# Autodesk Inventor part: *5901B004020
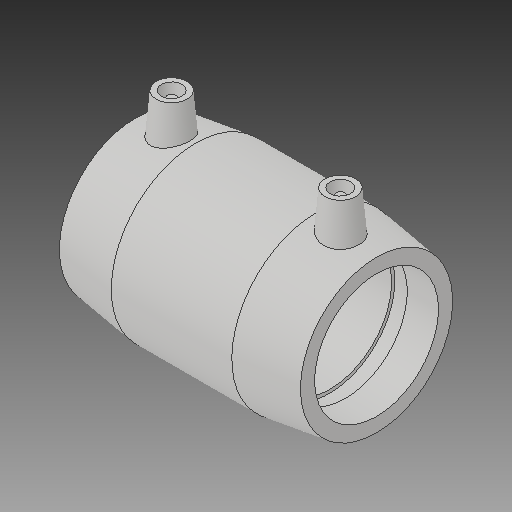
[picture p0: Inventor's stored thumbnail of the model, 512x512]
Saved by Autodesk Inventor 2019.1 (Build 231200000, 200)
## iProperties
Created: 2017-06
Part Number: *5901B004020
Material: Generic
Description: PLASSON IPS COUPLER 2''
Document SubType Name: Modeling
Designer: KIM
Mass: 8622.19 g
Surface Area: 6772.47 cm^2
Volume: 8622.19 cm^3
Density: 1 g/cm^3
Appearance: Default
Author: KIM
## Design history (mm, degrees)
derived "5901B.ipt"
feature "Solid1::5901B.ipt"
tag "TaggingFeature1"
body "Solid1"
other parameters: "d0" = 117.094, "d1" = 60.1, "d2" = 82.042, "d3" = 56.896, "d4" = 29.2735, "d5" = 73.8378, "d6" = 48.08, "d7" = 60.1, "d8" = 168 deg, "d10" = 22.7584, "d11" = 7.58613, "d13" = 117.094, "d14" = 17.6296, "d18" = 60.1, "d19" = 3.52592, "d20" = 168 deg, "d22" = 77.11948, "d23" = 82.042, "d24" = 74.8059, "d25" = 135 deg, "d26" = 52.6923, "d27" = 135 deg, "d29" = 57.404, "d30" = 15, "d31" = 40.9829, "d34" = 5 deg, "d35" = 15, "d39" = 5 deg, "d41" = 4, "d42" = 14, "d43" = 0, "d45" = 4, "d46" = 14, "d47" = 0, "d48" = 3, "d49" = 0, "d50" = 3, "d51" = 0, "d52" = 16.49984, "d53" = 4.12496, "d55" = 56.896, "d_" = 60.1, "L_" = 117.094, "L_1" = 56.896, "D_" = 82.042, "A_" = 57.404, "d_2" = 12, "B_" = 57.404
